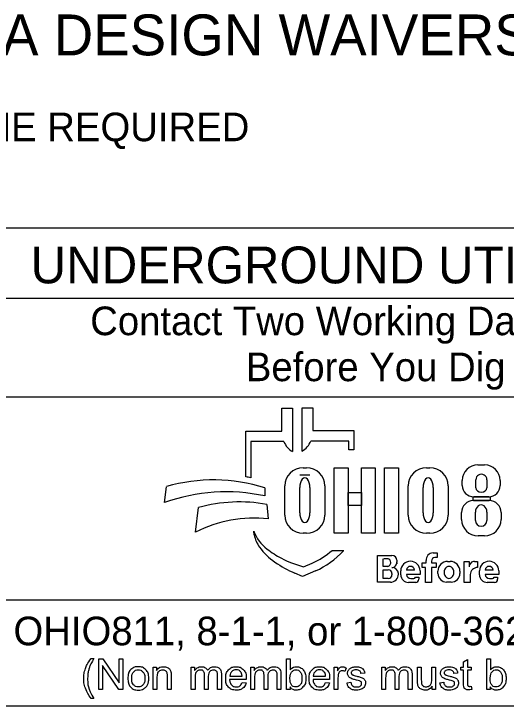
# Model space of a CAD drawing. Extents: x 0 to 34, y 0 to 22.
# Drawn here: x 2.424 to 4.831, y 2.143 to 5.529 of the extents above; entities that cross this region are included whole.
import ezdxf

# ---------------------------------------------------------------- set-up
doc = ezdxf.new("R2010")
doc.units = 0
doc.layers.add('SH_Data', color=7, linetype='Continuous')
doc.layers.add('SH_Text', color=7, linetype='Continuous')

msp = doc.modelspace()

# ---------------------------------------------------------------- linework, layer by layer
at = {"layer": 'SH_Data'}
for p, q in [((6.6275, 4.4803), (2.3775, 4.4803)), ((2.3775, 4.1387), (6.6275, 4.1387)), ((2.3775, 3.6553), (6.6275, 3.6553)), ((6.6275, 2.6607), (2.3775, 2.6607)), ((6.6275, 2.1428), (2.3775, 2.1428))]:
    msp.add_line(p, q, dxfattribs=at)
at = {"layer": 'SH_Text'}
for p, q in [((3.7335, 3.4883), (3.7335, 3.5998)), ((3.7335, 3.5998), (3.7872, 3.5998)), ((3.7872, 3.5998), (3.7872, 3.3877)), ((3.8329, 3.39), (3.8329, 3.6021)), ((3.8329, 3.6021), (3.8865, 3.6021)), ((3.8865, 3.6021), (3.8865, 3.4906)), ((3.5576, 3.2644), (3.5576, 3.4883)), ((3.5576, 3.4883), (3.7335, 3.4883)), ((3.8865, 3.4906), (4.0857, 3.4906)), ((4.0857, 3.4906), (4.0857, 3.3968)), ((3.5828, 3.4369), (3.5828, 3.26)), ((3.7439, 3.4369), (3.5828, 3.4369)), ((4.0625, 3.4392), (3.8761, 3.4392)), ((4.0625, 3.3968), (4.0625, 3.4392)), ((4.0857, 3.3968), (4.0625, 3.3968)), ((4.6931, 3.3231), (4.7258, 3.3231)), ((3.8385, 3.3091), (3.8551, 3.3091)), ((4.4416, 3.3091), (4.4581, 3.3091)), ((3.8718, 3.2721), (3.822, 3.2721)), ((4.683, 3.2111), (4.683, 3.2504)), ((4.7371, 3.2504), (4.7371, 3.2111)), ((3.7491, 3.0776), (3.7491, 3.2196)), ((3.9445, 3.2196), (3.9445, 3.0776)), ((4.3521, 3.0776), (4.3521, 3.2196)), ((4.5476, 3.2196), (4.5476, 3.0776)), ((4.6168, 3.2225), (4.6168, 3.2468)), ((4.8022, 3.2468), (4.8022, 3.2225)), ((3.1602, 3.1381), (3.1696, 3.2162)), ((3.6509, 3.2097), (3.6509, 3.1709)), ((3.822, 3.089), (3.822, 3.2114)), ((3.8718, 3.2114), (3.8718, 3.089)), ((4.425, 3.089), (4.425, 3.2114)), ((4.4748, 3.2114), (4.4748, 3.089)), ((4.7462, 3.1665), (4.6728, 3.1665)), ((3.6608, 3.1291), (3.6671, 3.0582)), ((4.671, 3.1482), (4.7483, 3.1482)), ((3.312, 2.9936), (3.3267, 3.1137)), ((4.6131, 3.0563), (4.6131, 3.0903)), ((4.6806, 3.0503), (4.6806, 3.0912)), ((4.7374, 3.0912), (4.7374, 3.0503)), ((4.8062, 3.0903), (4.8062, 3.0563)), ((3.5997, 2.9807), (3.5967, 2.9986)), ((3.8551, 2.9882), (3.8385, 2.9882)), ((4.4581, 2.9882), (4.4416, 2.9882)), ((4.7252, 2.9753), (4.6941, 2.9753)), ((3.98, 2.9048), (4.0375, 2.9048)), ((4.2013, 2.749), (4.2013, 2.8798)), ((4.2013, 2.8798), (4.2725, 2.8798)), ((4.4739, 2.8926), (4.4934, 2.8926)), ((4.4934, 2.8926), (4.4934, 2.8696)), ((3.7816, 2.8444), (3.841, 2.8239)), ((4.2293, 2.8263), (4.2293, 2.8632)), ((4.2545, 2.8632), (4.2332, 2.8632)), ((4.2963, 2.856), (4.2963, 2.8481)), ((4.4213, 2.8212), (4.4213, 2.8442)), ((4.4213, 2.8442), (4.4406, 2.8442)), ((4.4406, 2.8442), (4.4406, 2.8546)), ((4.4667, 2.8526), (4.4667, 2.8442)), ((4.4667, 2.8442), (4.4883, 2.8442)), ((4.4934, 2.8691), (4.4832, 2.8691)), ((4.4883, 2.8442), (4.4883, 2.8212)), ((4.5451, 2.8508), (4.5573, 2.8508)), ((4.6254, 2.7478), (4.6254, 2.8505)), ((4.6254, 2.8505), (4.6499, 2.8505)), ((4.6499, 2.8505), (4.6499, 2.8237)), ((4.6772, 2.8505), (4.691, 2.8505)), ((4.691, 2.8505), (4.691, 2.8209)), ((3.841, 2.8239), (3.8821, 2.8417)), ((4.2487, 2.8263), (4.2293, 2.8263)), ((4.4362, 2.8212), (4.4213, 2.8212)), ((4.4362, 2.7478), (4.4362, 2.8212)), ((4.4883, 2.8212), (4.4667, 2.8212)), ((4.4667, 2.8212), (4.4667, 2.7478)), ((3.835, 2.7769), (3.7976, 2.7934)), ((3.8983, 2.8044), (3.835, 2.7769)), ((4.2293, 2.7669), (4.2293, 2.8097)), ((4.2293, 2.8097), (4.2548, 2.8097)), ((4.2729, 2.7916), (4.2729, 2.7853)), ((4.3043, 2.7887), (4.3043, 2.7884)), ((4.3159, 2.7858), (4.3159, 2.8042)), ((4.3824, 2.8082), (4.3439, 2.8082)), ((4.4104, 2.7866), (4.344, 2.7866)), ((4.4104, 2.8042), (4.4104, 2.7866)), ((4.4973, 2.7922), (4.4973, 2.8029)), ((4.6051, 2.8029), (4.6051, 2.7922)), ((4.6559, 2.786), (4.6559, 2.7478)), ((4.7008, 2.7858), (4.7008, 2.8042)), ((4.7674, 2.8082), (4.7288, 2.8082)), ((4.7953, 2.7866), (4.7289, 2.7866)), ((4.7953, 2.8042), (4.7953, 2.7866)), ((4.265, 2.749), (4.2013, 2.749)), ((4.2546, 2.7669), (4.2293, 2.7669)), ((4.3892, 2.7478), (4.3538, 2.7478)), ((4.3649, 2.7673), (4.379, 2.7673)), ((4.3876, 2.7729), (4.4045, 2.7729)), ((4.4045, 2.7729), (4.4045, 2.7631)), ((4.4667, 2.7478), (4.4362, 2.7478)), ((4.5623, 2.7494), (4.5401, 2.7494)), ((4.6559, 2.7478), (4.6254, 2.7478)), ((4.7742, 2.7478), (4.7388, 2.7478)), ((4.7498, 2.7673), (4.7639, 2.7673)), ((4.7725, 2.7729), (4.7894, 2.7729)), ((4.7894, 2.7729), (4.7894, 2.7631))]:
    msp.add_line(p, q, dxfattribs=at)
for points in [[(3.991, 3.3081), (4.0589, 3.3081), (4.0589, 2.9881), (3.991, 2.9881)], [(4.1231, 3.3081), (4.1911, 3.3081), (4.1911, 2.9881), (4.1231, 2.9881)], [(4.2364, 3.3081), (4.3052, 3.3081), (4.3052, 2.9881), (4.2364, 2.9881)], [(4.0589, 3.1882), (4.1231, 3.1882), (4.1231, 3.1242), (4.0589, 3.1242)], [(4.6706, 3.1665), (4.7523, 3.1665), (4.7523, 3.1481), (4.6706, 3.1481)]]:
    msp.add_lwpolyline(points, close=True, dxfattribs=at)
for points in [[(2.8021, 2.3766), (2.8153, 2.3766)], [(2.8389, 2.2239), (2.8389, 2.3741), (2.8592, 2.3741), (2.9382, 2.2561), (2.9382, 2.3741), (2.9572, 2.3741), (2.9572, 2.2239), (2.9369, 2.2239), (2.8579, 2.3419), (2.8579, 2.2239), (2.8389, 2.2239)], [(3.7743, 2.2239), (3.7573, 2.2239), (3.7573, 2.3741), (3.7757, 2.3741), (3.7757, 2.3206)], [(4.6233, 2.2558), (4.6233, 2.3185), (4.6097, 2.3185), (4.6097, 2.3328), (4.6233, 2.3328), (4.6233, 2.3597), (4.6417, 2.3708), (4.6417, 2.3328), (4.6601, 2.3328), (4.6601, 2.3185), (4.6417, 2.3185), (4.6417, 2.2547)], [(4.7534, 2.2239), (4.7363, 2.2239), (4.7363, 2.3741), (4.7548, 2.3741), (4.7548, 2.3206)], [(3.1048, 2.2239), (3.1048, 2.3328), (3.1214, 2.3328), (3.1214, 2.3173)], [(3.2912, 2.2239), (3.2912, 2.3328), (3.3077, 2.3328), (3.3077, 2.3174)], [(3.5826, 2.2239), (3.5826, 2.3328), (3.5991, 2.3328), (3.5991, 2.3174)], [(3.9904, 2.2239), (3.9904, 2.3328), (4.007, 2.3328), (4.007, 2.3163)], [(4.0495, 2.3293), (4.043, 2.3122)], [(4.1394, 2.3046), (4.1213, 2.3022)], [(4.2236, 2.2239), (4.2236, 2.3328), (4.2401, 2.3328), (4.2401, 2.3174)], [(4.3979, 2.2654), (4.3979, 2.3328), (4.4164, 2.3328), (4.4164, 2.2724)], [(4.4676, 2.2745), (4.4676, 2.3328), (4.4861, 2.3328), (4.4861, 2.2239), (4.4696, 2.2239)], [(4.594, 2.3046), (4.5759, 2.3022)], [(3.1233, 2.2833), (3.1233, 2.2239), (3.1048, 2.2239)], [(3.1932, 2.2908), (3.1932, 2.2239), (3.1748, 2.2239), (3.1748, 2.2901)], [(3.3097, 2.2803), (3.3097, 2.2239), (3.2912, 2.2239)], [(3.3743, 2.2871), (3.3743, 2.2239), (3.3559, 2.2239), (3.3559, 2.2946)], [(3.4388, 2.2986), (3.4388, 2.2239), (3.4203, 2.2239), (3.4203, 2.2924)], [(3.56, 2.2736), (3.4788, 2.2736)], [(3.4799, 2.2887), (3.5406, 2.2887)], [(3.601, 2.2803), (3.601, 2.2239), (3.5826, 2.2239)], [(3.6657, 2.2871), (3.6657, 2.2239), (3.6473, 2.2239), (3.6473, 2.2946)], [(3.7301, 2.2986), (3.7301, 2.2239), (3.7117, 2.2239), (3.7117, 2.2924)], [(3.968, 2.2736), (3.8868, 2.2736)], [(3.8879, 2.2887), (3.9486, 2.2887)], [(4.0088, 2.2809), (4.0088, 2.2239), (3.9904, 2.2239)], [(4.242, 2.2803), (4.242, 2.2239), (4.2236, 2.2239)], [(4.3067, 2.2871), (4.3067, 2.2239), (4.2883, 2.2239), (4.2883, 2.2946)], [(4.3711, 2.2986), (4.3711, 2.2239), (4.3527, 2.2239), (4.3527, 2.2924)], [(3.5404, 2.2591), (3.5595, 2.2567)], [(3.7743, 2.2375), (3.7743, 2.2239)], [(3.9484, 2.2591), (3.9675, 2.2567)], [(4.053, 2.2564), (4.0712, 2.2593)], [(4.4696, 2.2239), (4.4696, 2.24)], [(4.5076, 2.2564), (4.5258, 2.2593)], [(4.6601, 2.2404), (4.6628, 2.2241)], [(4.7534, 2.2375), (4.7534, 2.2239)], [(2.8153, 2.1798), (2.8021, 2.1798)]]:
    msp.add_lwpolyline(points, dxfattribs=at)
for centre, radius, start, end in [((3.8353, 3.4736), 0.0985, 201.9296, 240.7469), ((3.7847, 3.476), 0.0985, 299.2531, 338.0704), ((4.6931, 3.2468), 0.0763, 90, 180), ((4.7258, 3.2468), 0.0763, 0, 90), ((3.8385, 3.2196), 0.0895, 90, 180), ((3.8551, 3.2196), 0.0895, 0, 90), ((4.4416, 3.2196), 0.0895, 90, 180), ((4.4581, 3.2196), 0.0895, 0, 90), ((3.4295, 2.4554), 0.8191, 79.2074, 81.0007), ((3.3997, 2.4302), 0.8191, 72.1402, 106.3144), ((4.6728, 3.2225), 0.056, 180, 270), ((4.7462, 3.2225), 0.056, 270, 0), ((3.4628, 2.2991), 0.8919, 77.8238, 109.8274), ((3.5267, 2.4094), 0.7322, 79.44, 105.8467), ((4.671, 3.0903), 0.0579, 90, 180), ((4.7483, 3.0903), 0.0579, 0, 90), ((3.5987, 2.4262), 0.6357, 83.8248, 116.8021), ((3.8385, 3.0776), 0.0895, 180, 270), ((3.8551, 3.0776), 0.0895, 270, 0), ((4.4416, 3.0776), 0.0895, 180, 270), ((4.4581, 3.0776), 0.0895, 270, 0), ((4.6941, 3.0563), 0.081, 180, 270), ((4.7252, 3.0563), 0.081, 270, 0), ((3.7841, 3.0707), 0.2008, 201.0457, 232.5314), ((3.741, 3.0048), 0.1433, 189.6817, 216.0884), ((3.8747, 3.1022), 0.3088, 216.0884, 235.7167), ((3.9766, 3.3219), 0.5173, 232.5314, 241.794), ((3.7387, 3.1722), 0.3602, 293.4582, 312.0712), ((3.7387, 3.1722), 0.401, 293.4582, 317.8286), ((4.2725, 2.856), 0.0238, 0, 90), ((4.4739, 2.859), 0.0335, 90, 187.5187), ((4.0412, 3.3465), 0.6044, 235.7167, 246.2325), ((3.8914, 3.1631), 0.3371, 241.794, 250.9821), ((4.2487, 2.845), 0.0187, 270, 2.0582), ((4.2505, 2.8463), 0.0169, 357.8325, 90), ((4.2721, 2.8453), 0.0243, 270, 6.6529), ((4.3631, 2.8042), 0.0473, 0, 180), ((4.4832, 2.8526), 0.0165, 90, 180), ((4.5451, 2.8029), 0.0478, 90, 180), ((4.5573, 2.8029), 0.0478, 0, 90), ((4.6768, 2.8237), 0.0269, 89.2449, 180), ((4.7481, 2.8042), 0.0473, 0, 180), ((4.2722, 2.7889), 0.0321, 4.0748, 90), ((4.2827, 2.8438), 0.0175, 347.4023, 0), ((4.3632, 2.8072), 0.0193, 2.9632, 177.0368), ((4.6908, 2.786), 0.0349, 89.6033, 180), ((4.7481, 2.8072), 0.0193, 2.9632, 177.0368), ((4.2546, 2.7853), 0.0184, 270, 0), ((4.2548, 2.7916), 0.0181, 0, 90), ((4.265, 2.7884), 0.0393, 270, 0), ((4.2714, 2.7887), 0.033, 0, 11.7502), ((4.3538, 2.7858), 0.038, 180, 270), ((4.3649, 2.7883), 0.021, 184.827, 270), ((4.5401, 2.7922), 0.0428, 180, 270), ((4.5623, 2.7922), 0.0428, 270, 0), ((4.7388, 2.7858), 0.038, 180, 270), ((4.7498, 2.7883), 0.021, 184.827, 270), ((4.379, 2.7767), 0.00938, 270, 335.9979), ((4.3892, 2.7631), 0.0152, 270, 0), ((4.7639, 2.7767), 0.00938, 270, 335.9979), ((4.7742, 2.7631), 0.0152, 270, 0)]:
    msp.add_arc(centre, radius, start, end, dxfattribs=at)
for centre, major_axis, ratio, start_param, end_param in [((3.8469, 3.2114), (0, 0.0484), 0.514403, 4.712389, 7.853982), ((4.4499, 3.2114), (0, 0.0484), 0.514403, 4.712389, 7.853982), ((4.71, 3.2504), (0.0271, 0), 0.969373, 0, 3.141593), ((4.71, 3.2111), (0.0271, 0), 0.818453, 3.141593, 6.283185), ((4.709, 3.0912), (0, 0.0358), 0.794529, 4.712389, 7.853982), ((3.8469, 3.089), (0, 0.0484), 0.514403, 1.570796, 4.712389), ((4.4499, 3.089), (0, 0.0484), 0.514403, 1.570796, 4.712389), ((4.709, 3.0503), (0.0284, 0), 0.959837, 3.141593, 6.283185), ((4.5517, 2.7976), (0, 0.029), 0.832186, 4.712389, 7.853982), ((4.5517, 2.7976), (0, 0.0302), 0.797287, 1.570796, 4.712389)]:
    msp.add_ellipse(centre, major_axis=major_axis, ratio=ratio, start_param=start_param, end_param=end_param, dxfattribs=at)
for points in [[(2.8021, 2.1798), (2.7869, 2.199), (2.7763, 2.2248), (2.7657, 2.2506), (2.7657, 2.2783), (2.7657, 2.3026), (2.7736, 2.325), (2.7829, 2.3509), (2.8021, 2.3766)], [(2.8153, 2.3766), (2.8029, 2.3553), (2.7989, 2.3462), (2.7927, 2.332), (2.7891, 2.3167), (2.7847, 2.2975), (2.7847, 2.2782), (2.7847, 2.2289), (2.8153, 2.1798)], [(2.9814, 2.2783), (2.9814, 2.3085), (2.9981, 2.3231), (3.0122, 2.3352), (3.0323, 2.3352), (3.0547, 2.3352), (3.069, 2.3205), (3.0832, 2.3058), (3.0832, 2.2799), (3.0832, 2.2589), (3.0769, 2.2469), (3.0706, 2.2348), (3.0586, 2.2282), (3.0466, 2.2215), (3.0323, 2.2215), (3.0095, 2.2215), (2.9954, 2.2362), (2.9814, 2.2508), (2.9814, 2.2783)], [(3.0003, 2.2783), (3.0003, 2.2574), (3.0094, 2.247), (3.0185, 2.2366), (3.0323, 2.2366), (3.046, 2.2366), (3.0551, 2.2471), (3.0642, 2.2575), (3.0642, 2.279), (3.0642, 2.2991), (3.0551, 2.3095), (3.0459, 2.3199), (3.0323, 2.3199), (3.0185, 2.3199), (3.0094, 2.3096), (3.0003, 2.2992), (3.0003, 2.2783)], [(3.1214, 2.3173), (3.1334, 2.3352), (3.156, 2.3352), (3.1659, 2.3352), (3.1741, 2.3316), (3.1823, 2.3281), (3.1864, 2.3224), (3.1905, 2.3166), (3.1922, 2.3087), (3.1932, 2.3036), (3.1932, 2.2908)], [(3.1748, 2.2901), (3.1748, 2.3013), (3.1726, 2.3069), (3.1705, 2.3125), (3.165, 2.3158), (3.1595, 2.3191), (3.1521, 2.3191), (3.1404, 2.3191), (3.1318, 2.3117), (3.1233, 2.3042), (3.1233, 2.2833)], [(3.3077, 2.3174), (3.3128, 2.3254), (3.3214, 2.3303), (3.3299, 2.3352), (3.3407, 2.3352), (3.3528, 2.3352), (3.3606, 2.3301), (3.3683, 2.3251), (3.3715, 2.3161), (3.3844, 2.3352), (3.4051, 2.3352), (3.4213, 2.3352), (3.43, 2.3262), (3.4388, 2.3172), (3.4388, 2.2986)], [(3.3559, 2.2946), (3.3559, 2.3069), (3.3514, 2.313), (3.3469, 2.3191), (3.3366, 2.3191), (3.3288, 2.3191), (3.3222, 2.315), (3.3156, 2.311), (3.3126, 2.3031), (3.3097, 2.2952), (3.3097, 2.2803)], [(3.4203, 2.2924), (3.4203, 2.3035), (3.4185, 2.3083), (3.4168, 2.3132), (3.412, 2.3162), (3.4073, 2.3191), (3.401, 2.3191), (3.3895, 2.3191), (3.3819, 2.3115), (3.3743, 2.3039), (3.3743, 2.2871)], [(3.5595, 2.2567), (3.555, 2.24), (3.5428, 2.2307), (3.5306, 2.2215), (3.5117, 2.2215), (3.4878, 2.2215), (3.4738, 2.2362), (3.4598, 2.2509), (3.4598, 2.2774), (3.4598, 2.3049), (3.474, 2.32), (3.4881, 2.3352), (3.5106, 2.3352), (3.5324, 2.3352), (3.5463, 2.3203), (3.5601, 2.3055), (3.5601, 2.2785), (3.5601, 2.2769), (3.56, 2.2736)], [(3.5406, 2.2887), (3.5394, 2.3025), (3.5337, 2.3094), (3.5249, 2.3201), (3.5108, 2.3201), (3.4981, 2.3201), (3.4894, 2.3115), (3.4808, 2.303), (3.4799, 2.2887)], [(3.5991, 2.3174), (3.6042, 2.3254), (3.6127, 2.3303), (3.6212, 2.3352), (3.6321, 2.3352), (3.6442, 2.3352), (3.6519, 2.3301), (3.6597, 2.3251), (3.6628, 2.3161), (3.6758, 2.3352), (3.6965, 2.3352), (3.7127, 2.3352), (3.7214, 2.3262), (3.7301, 2.3172), (3.7301, 2.2986)], [(3.6473, 2.2946), (3.6473, 2.3069), (3.6428, 2.313), (3.6383, 2.3191), (3.628, 2.3191), (3.6202, 2.3191), (3.6136, 2.315), (3.607, 2.311), (3.604, 2.3031), (3.601, 2.2952), (3.601, 2.2803)], [(3.7117, 2.2924), (3.7117, 2.3035), (3.7099, 2.3083), (3.7081, 2.3132), (3.7034, 2.3162), (3.6987, 2.3191), (3.6923, 2.3191), (3.6809, 2.3191), (3.6733, 2.3115), (3.6657, 2.3039), (3.6657, 2.2871)], [(3.7741, 2.2792), (3.7741, 2.2596), (3.7794, 2.2509), (3.7881, 2.2366), (3.8029, 2.2366), (3.815, 2.2366), (3.8238, 2.2471), (3.8326, 2.2576), (3.8326, 2.2784), (3.8326, 2.2998), (3.8241, 2.3099), (3.8157, 2.3201), (3.8038, 2.3201), (3.7917, 2.3201), (3.7829, 2.3096), (3.7741, 2.299), (3.7741, 2.2792)], [(3.7757, 2.3206), (3.7874, 2.3352), (3.8055, 2.3352), (3.8155, 2.3352), (3.8245, 2.3311), (3.8335, 2.3271), (3.8392, 2.3198), (3.845, 2.3124), (3.8483, 2.3021), (3.8516, 2.2918), (3.8516, 2.28), (3.8516, 2.252), (3.8378, 2.2368), (3.8239, 2.2215), (3.8046, 2.2215), (3.7853, 2.2215), (3.7743, 2.2375)], [(3.9675, 2.2567), (3.963, 2.24), (3.9508, 2.2307), (3.9386, 2.2215), (3.9196, 2.2215), (3.8958, 2.2215), (3.8818, 2.2362), (3.8678, 2.2509), (3.8678, 2.2774), (3.8678, 2.3049), (3.882, 2.32), (3.8961, 2.3352), (3.9186, 2.3352), (3.9404, 2.3352), (3.9543, 2.3203), (3.9681, 2.3055), (3.9681, 2.2785), (3.9681, 2.2769), (3.968, 2.2736)], [(3.9486, 2.2887), (3.9474, 2.3025), (3.9417, 2.3094), (3.9328, 2.3201), (3.9188, 2.3201), (3.9061, 2.3201), (3.8974, 2.3115), (3.8888, 2.303), (3.8879, 2.2887)], [(4.007, 2.3163), (4.0133, 2.3278), (4.0187, 2.3315), (4.0241, 2.3352), (4.0305, 2.3352), (4.0398, 2.3352), (4.0495, 2.3293)], [(4.043, 2.3122), (4.0363, 2.3162), (4.0295, 2.3162), (4.0235, 2.3162), (4.0187, 2.3125), (4.0139, 2.3089), (4.0119, 2.3024), (4.0088, 2.2926), (4.0088, 2.2809)], [(4.1213, 2.3022), (4.1201, 2.3106), (4.1142, 2.3153), (4.1083, 2.3201), (4.0975, 2.3201), (4.0848, 2.3201), (4.0794, 2.3159), (4.0739, 2.3116), (4.0739, 2.306), (4.0739, 2.3024), (4.0762, 2.2995), (4.0785, 2.2966), (4.0833, 2.2946), (4.086, 2.2936), (4.0996, 2.2899), (4.1192, 2.2847), (4.1269, 2.2813), (4.1347, 2.278), (4.1391, 2.2717), (4.1435, 2.2653), (4.1435, 2.2559), (4.1435, 2.2467), (4.1381, 2.2386), (4.1327, 2.2304), (4.1226, 2.226), (4.1124, 2.2215), (4.0996, 2.2215), (4.0784, 2.2215), (4.0672, 2.2303), (4.0561, 2.2391), (4.053, 2.2564)], [(4.0712, 2.2593), (4.0727, 2.2483), (4.0798, 2.2425), (4.0868, 2.2366), (4.0995, 2.2366), (4.1122, 2.2366), (4.1184, 2.2418), (4.1245, 2.247), (4.1245, 2.254), (4.1245, 2.2602), (4.1191, 2.2638), (4.1153, 2.2663), (4.1002, 2.2701), (4.0799, 2.2752), (4.072, 2.2789), (4.0642, 2.2827), (4.0601, 2.2893), (4.0561, 2.2959), (4.0561, 2.3038), (4.0561, 2.3111), (4.0594, 2.3173), (4.0628, 2.3235), (4.0685, 2.3276), (4.0728, 2.3308), (4.0803, 2.333), (4.0877, 2.3352), (4.0962, 2.3352), (4.109, 2.3352), (4.1187, 2.3315), (4.1284, 2.3278), (4.133, 2.3215), (4.1377, 2.3152), (4.1394, 2.3046)], [(4.2401, 2.3174), (4.2452, 2.3254), (4.2537, 2.3303), (4.2622, 2.3352), (4.2731, 2.3352), (4.2852, 2.3352), (4.2929, 2.3301), (4.3007, 2.3251), (4.3038, 2.3161), (4.3168, 2.3352), (4.3375, 2.3352), (4.3537, 2.3352), (4.3624, 2.3262), (4.3711, 2.3172), (4.3711, 2.2986)], [(4.2883, 2.2946), (4.2883, 2.3069), (4.2838, 2.313), (4.2793, 2.3191), (4.269, 2.3191), (4.2612, 2.3191), (4.2546, 2.315), (4.248, 2.311), (4.245, 2.3031), (4.242, 2.2952), (4.242, 2.2803)], [(4.3527, 2.2924), (4.3527, 2.3035), (4.3509, 2.3083), (4.3491, 2.3132), (4.3444, 2.3162), (4.3397, 2.3191), (4.3333, 2.3191), (4.3219, 2.3191), (4.3143, 2.3115), (4.3067, 2.3039), (4.3067, 2.2871)], [(4.5759, 2.3022), (4.5747, 2.3106), (4.5688, 2.3153), (4.5629, 2.3201), (4.5521, 2.3201), (4.5394, 2.3201), (4.5339, 2.3159), (4.5285, 2.3116), (4.5285, 2.306), (4.5285, 2.3024), (4.5308, 2.2995), (4.533, 2.2966), (4.5378, 2.2946), (4.5406, 2.2936), (4.5542, 2.2899), (4.5737, 2.2847), (4.5815, 2.2813), (4.5893, 2.278), (4.5937, 2.2717), (4.5981, 2.2653), (4.5981, 2.2559), (4.5981, 2.2467), (4.5927, 2.2386), (4.5873, 2.2304), (4.5772, 2.226), (4.567, 2.2215), (4.5542, 2.2215), (4.5329, 2.2215), (4.5218, 2.2303), (4.5107, 2.2391), (4.5076, 2.2564)], [(4.5258, 2.2593), (4.5273, 2.2483), (4.5343, 2.2425), (4.5414, 2.2366), (4.554, 2.2366), (4.5668, 2.2366), (4.5729, 2.2418), (4.5791, 2.247), (4.5791, 2.254), (4.5791, 2.2602), (4.5736, 2.2638), (4.5698, 2.2663), (4.5548, 2.2701), (4.5345, 2.2752), (4.5266, 2.2789), (4.5188, 2.2827), (4.5147, 2.2893), (4.5107, 2.2959), (4.5107, 2.3038), (4.5107, 2.3111), (4.514, 2.3173), (4.5173, 2.3235), (4.5231, 2.3276), (4.5274, 2.3308), (4.5348, 2.333), (4.5423, 2.3352), (4.5508, 2.3352), (4.5636, 2.3352), (4.5733, 2.3315), (4.583, 2.3278), (4.5876, 2.3215), (4.5922, 2.3152), (4.594, 2.3046)], [(4.7532, 2.2792), (4.7532, 2.2596), (4.7585, 2.2509), (4.7672, 2.2366), (4.782, 2.2366), (4.7941, 2.2366), (4.8029, 2.2471), (4.8116, 2.2576), (4.8116, 2.2784), (4.8116, 2.2998), (4.8032, 2.3099), (4.7948, 2.3201), (4.7828, 2.3201), (4.7708, 2.3201), (4.762, 2.3096), (4.7532, 2.299), (4.7532, 2.2792)], [(4.7548, 2.3206), (4.7664, 2.3352), (4.7846, 2.3352), (4.7946, 2.3352), (4.8036, 2.3311), (4.8125, 2.3271), (4.8183, 2.3198), (4.8241, 2.3124), (4.8274, 2.3021), (4.8306, 2.2918), (4.8306, 2.28), (4.8306, 2.252), (4.8168, 2.2368), (4.803, 2.2215), (4.7836, 2.2215), (4.7644, 2.2215), (4.7534, 2.2375)], [(3.4788, 2.2736), (3.4799, 2.2557), (3.489, 2.2462), (3.4981, 2.2366), (3.5117, 2.2366), (3.5219, 2.2366), (3.5291, 2.242), (3.5362, 2.2473), (3.5404, 2.2591)], [(3.8868, 2.2736), (3.8879, 2.2557), (3.897, 2.2462), (3.9061, 2.2366), (3.9197, 2.2366), (3.9299, 2.2366), (3.937, 2.242), (3.9442, 2.2473), (3.9484, 2.2591)], [(4.4164, 2.2724), (4.4164, 2.258), (4.4175, 2.253), (4.4192, 2.2457), (4.4249, 2.2416), (4.4305, 2.2374), (4.4388, 2.2374), (4.4471, 2.2374), (4.4543, 2.2417), (4.4616, 2.2459), (4.4646, 2.2533), (4.4676, 2.2606), (4.4676, 2.2745)], [(4.4696, 2.24), (4.4569, 2.2215), (4.4351, 2.2215), (4.4255, 2.2215), (4.4171, 2.2252), (4.4088, 2.2289), (4.4047, 2.2345), (4.4007, 2.2401), (4.3991, 2.2482), (4.3979, 2.2536), (4.3979, 2.2654)], [(4.6628, 2.2241), (4.655, 2.2224), (4.6488, 2.2224), (4.6388, 2.2224), (4.6333, 2.2256), (4.6278, 2.2288), (4.6255, 2.234), (4.6233, 2.2392), (4.6233, 2.2558)], [(4.6417, 2.2547), (4.6417, 2.2468), (4.6427, 2.2445), (4.6436, 2.2423), (4.6458, 2.2409), (4.648, 2.2396), (4.6521, 2.2396), (4.6551, 2.2396), (4.6601, 2.2404)]]:
    msp.add_open_spline(points, degree=3, dxfattribs=at)

# ---------------------------------------------------------------- texts
for s, height, p in [('ADA DESIGN WAIVERS', 0.2, (1.9944, 5.3256)), ('NONE REQUIRED', 0.14, (1.9944, 4.9056)), ('UNDERGROUND UTILITIES', 0.18, (2.5057, 4.2106)), ('Contact Two Working Days', 0.14, (2.7972, 3.9571)), ('Before You Dig', 0.14, (3.5583, 3.7321)), ('OHIO811, 8-1-1, or 1-800-362-2764', 0.14, (2.422, 2.4406))]:
    msp.add_text(s, height=height, dxfattribs=at).set_placement(p)

doc.saveas('drawing.dxf')
